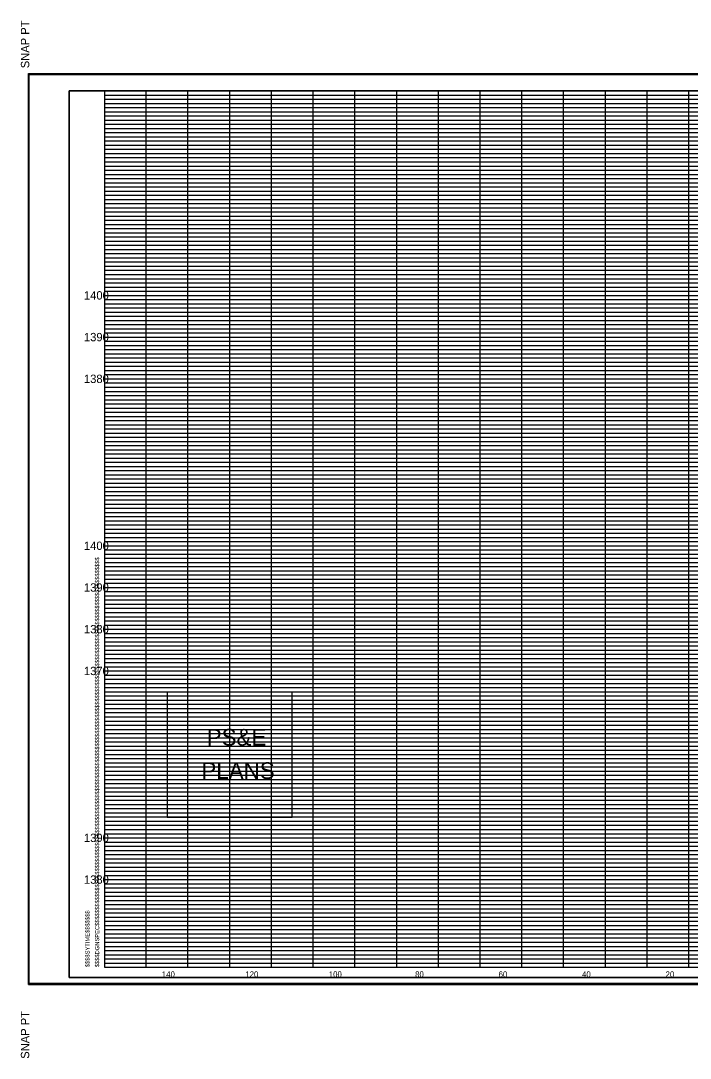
# Model space of a CAD drawing. Extents: x 980 to 1324, y 978 to 1497.
# Drawn here: x 979.9 to 1140.3, y 978.2 to 1226.8 of the extents above; entities that cross this region are included whole.
import ezdxf

# ---------------------------------------------------------------- set-up
doc = ezdxf.new("R2010")
doc.units = 0
for name, color, linetype in [('DESIGN - SHEET - Corner Text', 7, 'Continuous'), ('DESIGN - SHEET - Light Grid', 7, 'Continuous'), ('DESIGN - SHEET - Linework', 7, 'Continuous'), ('DESIGN - SHEET - Plot Shape', 7, 'Continuous'), ('DESIGN - TYPICAL - Text', 7, 'Continuous')]:
    doc.layers.add(name, color=color, linetype=linetype)

# ---------------------------------------------------------------- blocks, each defined once
blk = doc.blocks.new('XSTSHT')
at = {"layer": 'DESIGN - SHEET - Light Grid'}
for p, q in [((0, 20.9), (8, 20.9)), ((8, 20.9), (16, 20.9)), ((0, 20.8), (8, 20.8)), ((0, 20.7), (8, 20.7)), ((8, 20.8), (16, 20.8)), ((8, 20.7), (16, 20.7)), ((0, 20.6), (8, 20.6)), ((0, 20.5), (8, 20.5)), ((0, 20.4), (8, 20.4)), ((8, 20.6), (16, 20.6)), ((8, 20.5), (16, 20.5)), ((8, 20.4), (16, 20.4)), ((0, 20.3), (8, 20.3)), ((0, 20.2), (8, 20.2)), ((8, 20.3), (16, 20.3)), ((8, 20.2), (16, 20.2)), ((0, 20.1), (8, 20.1)), ((0, 19.9), (8, 19.9)), ((8, 20.1), (16, 20.1)), ((8, 19.9), (16, 19.9)), ((0, 19.8), (8, 19.8)), ((0, 19.7), (8, 19.7)), ((8, 19.8), (16, 19.8)), ((8, 19.7), (16, 19.7)), ((0, 19.6), (8, 19.6)), ((0, 19.5), (8, 19.5)), ((0, 19.4), (8, 19.4)), ((8, 19.6), (16, 19.6)), ((8, 19.5), (16, 19.5)), ((8, 19.4), (16, 19.4)), ((0, 19.3), (8, 19.3)), ((0, 19.2), (8, 19.2)), ((8, 19.3), (16, 19.3)), ((8, 19.2), (16, 19.2)), ((0, 19.1), (8, 19.1)), ((0, 18.9), (8, 18.9)), ((8, 19.1), (16, 19.1)), ((8, 18.9), (16, 18.9)), ((0, 18.8), (8, 18.8)), ((0, 18.7), (8, 18.7)), ((8, 18.8), (16, 18.8)), ((8, 18.7), (16, 18.7)), ((0, 18.6), (8, 18.6)), ((0, 18.5), (8, 18.5)), ((0, 18.4), (8, 18.4)), ((8, 18.6), (16, 18.6)), ((8, 18.5), (16, 18.5)), ((8, 18.4), (16, 18.4)), ((0, 18.3), (8, 18.3)), ((0, 18.2), (8, 18.2)), ((8, 18.3), (16, 18.3)), ((8, 18.2), (16, 18.2)), ((0, 18.1), (8, 18.1)), ((8, 18.1), (16, 18.1)), ((0, 17.9), (8, 17.9)), ((0, 17.8), (8, 17.8)), ((0, 17.7), (8, 17.7)), ((8, 17.9), (16, 17.9)), ((8, 17.8), (16, 17.8)), ((8, 17.7), (16, 17.7)), ((0, 17.6), (8, 17.6)), ((0, 17.5), (8, 17.5)), ((8, 17.6), (16, 17.6)), ((8, 17.5), (16, 17.5)), ((0, 17.4), (8, 17.4)), ((0, 17.3), (8, 17.3)), ((0, 17.2), (8, 17.2)), ((8, 17.4), (16, 17.4)), ((8, 17.3), (16, 17.3)), ((8, 17.2), (16, 17.2)), ((0, 17.1), (8, 17.1)), ((8, 17.1), (16, 17.1)), ((0, 16.9), (8, 16.9)), ((0, 16.8), (8, 16.8)), ((0, 16.7), (8, 16.7)), ((8, 16.9), (16, 16.9)), ((8, 16.8), (16, 16.8)), ((8, 16.7), (16, 16.7)), ((0, 16.6), (8, 16.6)), ((0, 16.5), (8, 16.5)), ((8, 16.6), (16, 16.6)), ((8, 16.5), (16, 16.5)), ((0, 16.4), (8, 16.4)), ((0, 16.3), (8, 16.3)), ((0, 16.2), (8, 16.2)), ((8, 16.4), (16, 16.4)), ((8, 16.3), (16, 16.3)), ((8, 16.2), (16, 16.2)), ((0, 16.1), (8, 16.1)), ((8, 16.1), (16, 16.1)), ((0, 15.9), (8, 15.9)), ((0, 15.8), (8, 15.8)), ((0, 15.7), (8, 15.7)), ((8, 15.9), (16, 15.9)), ((8, 15.8), (16, 15.8)), ((8, 15.7), (16, 15.7)), ((0, 15.6), (8, 15.6)), ((0, 15.5), (8, 15.5)), ((8, 15.6), (16, 15.6)), ((8, 15.5), (16, 15.5)), ((0, 15.4), (8, 15.4)), ((0, 15.3), (8, 15.3)), ((0, 15.2), (8, 15.2)), ((8, 15.4), (16, 15.4)), ((8, 15.3), (16, 15.3)), ((8, 15.2), (16, 15.2)), ((0, 15.1), (8, 15.1)), ((8, 15.1), (16, 15.1)), ((0, 14.9), (8, 14.9)), ((0, 14.8), (8, 14.8)), ((0, 14.7), (8, 14.7)), ((8, 14.9), (16, 14.9)), ((8, 14.8), (16, 14.8)), ((8, 14.7), (16, 14.7)), ((0, 14.6), (8, 14.6)), ((0, 14.5), (8, 14.5)), ((8, 14.6), (16, 14.6)), ((8, 14.5), (16, 14.5)), ((0, 14.4), (8, 14.4)), ((0, 14.3), (8, 14.3)), ((0, 14.2), (8, 14.2)), ((8, 14.4), (16, 14.4)), ((8, 14.3), (16, 14.3)), ((8, 14.2), (16, 14.2)), ((0, 14.1), (8, 14.1)), ((8, 14.1), (16, 14.1)), ((0, 13.9), (8, 13.9)), ((0, 13.8), (8, 13.8)), ((0, 13.7), (8, 13.7)), ((8, 13.9), (16, 13.9)), ((8, 13.8), (16, 13.8)), ((8, 13.7), (16, 13.7)), ((0, 13.6), (8, 13.6)), ((0, 13.5), (8, 13.5)), ((8, 13.6), (16, 13.6)), ((8, 13.5), (16, 13.5)), ((0, 13.4), (8, 13.4)), ((0, 13.3), (8, 13.3)), ((0, 13.2), (8, 13.2)), ((8, 13.4), (16, 13.4)), ((8, 13.3), (16, 13.3)), ((8, 13.2), (16, 13.2)), ((0, 13.1), (8, 13.1)), ((8, 13.1), (16, 13.1)), ((0, 12.9), (8, 12.9)), ((0, 12.8), (8, 12.8)), ((0, 12.7), (8, 12.7)), ((8, 12.9), (16, 12.9)), ((8, 12.8), (16, 12.8)), ((8, 12.7), (16, 12.7)), ((0, 12.6), (8, 12.6)), ((0, 12.5), (8, 12.5)), ((8, 12.6), (16, 12.6)), ((8, 12.5), (16, 12.5)), ((0, 12.4), (8, 12.4)), ((0, 12.3), (8, 12.3)), ((0, 12.2), (8, 12.2)), ((8, 12.4), (16, 12.4)), ((8, 12.3), (16, 12.3)), ((8, 12.2), (16, 12.2)), ((0, 12.1), (8, 12.1)), ((8, 12.1), (16, 12.1)), ((0, 11.9), (8, 11.9)), ((0, 11.8), (8, 11.8)), ((0, 11.7), (8, 11.7)), ((8, 11.9), (16, 11.9)), ((8, 11.8), (16, 11.8)), ((8, 11.7), (16, 11.7)), ((0, 11.6), (8, 11.6)), ((0, 11.5), (8, 11.5)), ((8, 11.6), (16, 11.6)), ((8, 11.5), (16, 11.5)), ((0, 11.4), (8, 11.4)), ((0, 11.3), (8, 11.3)), ((0, 11.2), (8, 11.2)), ((8, 11.4), (16, 11.4)), ((8, 11.3), (16, 11.3)), ((8, 11.2), (16, 11.2)), ((0, 11.1), (8, 11.1)), ((8, 11.1), (16, 11.1)), ((0, 10.9), (8, 10.9)), ((0, 10.8), (8, 10.8)), ((0, 10.7), (8, 10.7)), ((8, 10.9), (16, 10.9)), ((8, 10.8), (16, 10.8)), ((8, 10.7), (16, 10.7)), ((0, 10.6), (8, 10.6)), ((0, 10.5), (8, 10.5)), ((8, 10.6), (16, 10.6)), ((8, 10.5), (16, 10.5)), ((0, 10.4), (8, 10.4)), ((0, 10.3), (8, 10.3)), ((0, 10.2), (8, 10.2)), ((8, 10.4), (16, 10.4)), ((8, 10.3), (16, 10.3)), ((8, 10.2), (16, 10.2)), ((0, 10.1), (8, 10.1)), ((8, 10.1), (16, 10.1)), ((0, 9.9), (8, 9.9)), ((0, 9.8), (8, 9.8)), ((0, 9.7), (8, 9.7)), ((8, 9.9), (16, 9.9)), ((8, 9.8), (16, 9.8)), ((8, 9.7), (16, 9.7)), ((0, 9.6), (8, 9.6)), ((0, 9.5), (8, 9.5)), ((8, 9.6), (16, 9.6)), ((8, 9.5), (16, 9.5)), ((0, 9.4), (8, 9.4)), ((0, 9.3), (8, 9.3)), ((0, 9.2), (8, 9.2)), ((8, 9.4), (16, 9.4)), ((8, 9.3), (16, 9.3)), ((8, 9.2), (16, 9.2)), ((0, 9.1), (8, 9.1)), ((8, 9.1), (16, 9.1)), ((0, 8.9), (8, 8.9)), ((0, 8.8), (8, 8.8)), ((8, 8.9), (16, 8.9)), ((8, 8.8), (16, 8.8)), ((0, 8.7), (8, 8.7)), ((0, 8.6), (8, 8.6)), ((0, 8.5), (8, 8.5)), ((8, 8.7), (16, 8.7)), ((8, 8.6), (16, 8.6)), ((8, 8.5), (16, 8.5)), ((0, 8.4), (8, 8.4)), ((0, 8.3), (8, 8.3)), ((8, 8.4), (16, 8.4)), ((8, 8.3), (16, 8.3)), ((0, 8.2), (8, 8.2)), ((0, 8.1), (8, 8.1)), ((8, 8.2), (16, 8.2)), ((8, 8.1), (16, 8.1)), ((0, 7.9), (8, 7.9)), ((0, 7.8), (8, 7.8)), ((8, 7.9), (16, 7.9)), ((8, 7.8), (16, 7.8)), ((0, 7.7), (8, 7.7)), ((0, 7.6), (8, 7.6)), ((0, 7.5), (8, 7.5)), ((8, 7.7), (16, 7.7)), ((8, 7.6), (16, 7.6)), ((8, 7.5), (16, 7.5)), ((0, 7.4), (8, 7.4)), ((0, 7.3), (8, 7.3)), ((8, 7.4), (16, 7.4)), ((8, 7.3), (16, 7.3)), ((0, 7.2), (8, 7.2)), ((0, 7.1), (8, 7.1)), ((8, 7.2), (16, 7.2)), ((8, 7.1), (16, 7.1)), ((0, 6.9), (8, 6.9)), ((0, 6.8), (8, 6.8)), ((8, 6.9), (16, 6.9)), ((8, 6.8), (16, 6.8)), ((0, 6.7), (8, 6.7)), ((0, 6.6), (8, 6.6)), ((0, 6.5), (8, 6.5)), ((8, 6.7), (16, 6.7)), ((8, 6.6), (16, 6.6)), ((8, 6.5), (16, 6.5)), ((0, 6.4), (8, 6.4)), ((0, 6.3), (8, 6.3)), ((8, 6.4), (16, 6.4)), ((8, 6.3), (16, 6.3)), ((0, 6.2), (8, 6.2)), ((0, 6.1), (8, 6.1)), ((8, 6.2), (16, 6.2)), ((8, 6.1), (16, 6.1)), ((0, 5.9), (8, 5.9)), ((0, 5.8), (8, 5.8)), ((8, 5.9), (16, 5.9)), ((8, 5.8), (16, 5.8)), ((0, 5.7), (8, 5.7)), ((0, 5.6), (8, 5.6)), ((0, 5.5), (8, 5.5)), ((8, 5.7), (16, 5.7)), ((8, 5.6), (16, 5.6)), ((8, 5.5), (16, 5.5)), ((0, 5.4), (8, 5.4)), ((0, 5.3), (8, 5.3)), ((8, 5.4), (16, 5.4)), ((8, 5.3), (16, 5.3)), ((0, 5.2), (8, 5.2)), ((0, 5.1), (8, 5.1)), ((8, 5.2), (16, 5.2)), ((8, 5.1), (16, 5.1)), ((0, 4.9), (8, 4.9)), ((0, 4.8), (8, 4.8)), ((8, 4.9), (16, 4.9)), ((8, 4.8), (16, 4.8)), ((0, 4.7), (8, 4.7)), ((0, 4.6), (8, 4.6)), ((0, 4.5), (8, 4.5)), ((8, 4.7), (16, 4.7)), ((8, 4.6), (16, 4.6)), ((8, 4.5), (16, 4.5)), ((0, 4.4), (8, 4.4)), ((0, 4.3), (8, 4.3)), ((8, 4.4), (16, 4.4)), ((8, 4.3), (16, 4.3)), ((0, 4.2), (8, 4.2)), ((0, 4.1), (8, 4.1)), ((8, 4.2), (16, 4.2)), ((8, 4.1), (16, 4.1)), ((0, 3.9), (8, 3.9)), ((0, 3.8), (8, 3.8)), ((8, 3.9), (16, 3.9)), ((8, 3.8), (16, 3.8)), ((0, 3.7), (8, 3.7)), ((0, 3.6), (8, 3.6)), ((0, 3.5), (8, 3.5)), ((8, 3.7), (16, 3.7)), ((8, 3.6), (16, 3.6)), ((8, 3.5), (16, 3.5)), ((0, 3.4), (8, 3.4)), ((0, 3.3), (8, 3.3)), ((8, 3.4), (16, 3.4)), ((8, 3.3), (16, 3.3)), ((0, 3.2), (8, 3.2)), ((0, 3.1), (8, 3.1)), ((8, 3.2), (16, 3.2)), ((8, 3.1), (16, 3.1)), ((0, 2.9), (8, 2.9)), ((0, 2.8), (8, 2.8)), ((8, 2.9), (16, 2.9)), ((8, 2.8), (16, 2.8)), ((0, 2.7), (8, 2.7)), ((0, 2.6), (8, 2.6)), ((0, 2.5), (8, 2.5)), ((8, 2.7), (16, 2.7)), ((8, 2.6), (16, 2.6)), ((8, 2.5), (16, 2.5)), ((0, 2.4), (8, 2.4)), ((0, 2.3), (8, 2.3)), ((8, 2.4), (16, 2.4)), ((8, 2.3), (16, 2.3)), ((0, 2.2), (8, 2.2)), ((0, 2.1), (8, 2.1)), ((8, 2.2), (16, 2.2)), ((8, 2.1), (16, 2.1)), ((0, 1.9), (8, 1.9)), ((0, 1.8), (8, 1.8)), ((8, 1.9), (16, 1.9)), ((8, 1.8), (16, 1.8)), ((0, 1.7), (8, 1.7)), ((0, 1.6), (8, 1.6)), ((0, 1.5), (8, 1.5)), ((8, 1.7), (16, 1.7)), ((8, 1.6), (16, 1.6)), ((8, 1.5), (16, 1.5)), ((0, 1.4), (8, 1.4)), ((0, 1.3), (8, 1.3)), ((8, 1.4), (16, 1.4)), ((8, 1.3), (16, 1.3)), ((0, 1.2), (8, 1.2)), ((0, 1.1), (8, 1.1)), ((8, 1.2), (16, 1.2)), ((8, 1.1), (16, 1.1)), ((0, 0.9), (8, 0.9)), ((0, 0.8), (8, 0.8)), ((8, 0.9), (16, 0.9)), ((8, 0.8), (16, 0.8)), ((0, 0.7), (8, 0.7)), ((0, 0.6), (8, 0.6)), ((0, 0.5), (8, 0.5)), ((8, 0.7), (16, 0.7)), ((8, 0.6), (16, 0.6)), ((8, 0.5), (16, 0.5)), ((0, 0.4), (8, 0.4)), ((0, 0.3), (8, 0.3)), ((8, 0.4), (16, 0.4)), ((8, 0.3), (16, 0.3)), ((0, 0.2), (8, 0.2)), ((0, 0.1), (8, 0.1)), ((8, 0.2), (16, 0.2)), ((8, 0.1), (16, 0.1))]:
    blk.add_line(p, q, dxfattribs=at)
at = {"layer": 'DESIGN - SHEET - Linework'}
for p, q in [((-1.823, -0.414), (-1.823, 21.414)), ((-1.823, 21.414), (32.217, 21.414)), ((1, 0), (1, 21)), ((2, 0), (2, 21)), ((3, 0), (3, 21)), ((4, 0), (4, 21)), ((5, 0), (5, 21)), ((6, 0), (6, 21)), ((7, 0), (7, 21)), ((8, 0), (8, 21)), ((9, 0), (9, 21)), ((10, 0), (10, 21)), ((11, 0), (11, 21)), ((12, 0), (12, 21)), ((13, 0), (13, 21)), ((14, 0), (14, 21)), ((0, 20), (28, 20)), ((0, 19), (32, 19)), ((0, 18), (32, 18)), ((0, 17), (32, 17)), ((0, 16), (32, 16)), ((0, 15), (32, 15)), ((0, 14), (32, 14)), ((0, 13), (32, 13)), ((0, 12), (32, 12)), ((0, 11), (32, 11)), ((0, 10), (32, 10)), ((0, 9), (32, 9)), ((0, 8), (32, 8)), ((0, 7), (32, 7)), ((0, 6), (32, 6)), ((0, 5), (32, 5)), ((0, 4), (32, 4)), ((0, 3), (32, 3)), ((0, 2), (32, 2)), ((0, 1), (32, 1)), ((-1.823, -0.414), (32.217, -0.414))]:
    blk.add_line(p, q, dxfattribs=at)
blk.add_lwpolyline([(0, 21), (0, 0), (32, 0), (32, 21), (0, 21)], dxfattribs=at)
at = {"layer": 'DESIGN - SHEET - Plot Shape'}
for points in [[(-1.803, 21.394), (32.197, 21.394), (32.197, -0.394), (-1.803, -0.394)], [(-0.85, 21), (32, 21), (32, -0.25), (-0.85, -0.25)]]:
    blk.add_lwpolyline(points, close=True, dxfattribs=at)
at = {"layer": 'DESIGN - SHEET - Corner Text'}
for s, height, p in [('  SNAP PT', 0.2, (-1.803, 21.394)), ('$$$$DGNSPEC$$$$$$$$$$$$$$$$$$$$$$$$$$$$$$$$$$$$$$$$$$$$$$$$$$$$$$$$$$$$$$$$$$$$$$$$$$$$$$$$$$$$$$$$$$$$$$$$$$$$$$$$$$$$$$$$$$$', 0.100002, (-0.126, 0)), ('$$$$SYTIME$$$$$$$', 0.1, (-0.358, 0)), ('SNAP PT  ', 0.2, (-1.803, -2.194))]:
    blk.add_text(s, height=height, rotation=90, dxfattribs=at).set_placement(p)

msp = doc.modelspace()

# ---------------------------------------------------------------- linework, layer by layer
at = {"layer": 'DESIGN - SHEET - Corner Text'}
msp.add_lwpolyline([(1014.98, 1065.93), (1014.98, 1035.93), (1044.98, 1035.93), (1044.98, 1065.93)], close=True, dxfattribs=at)
at = {"layer": 'DESIGN - SHEET - Plot Shape'}
msp.add_lwpolyline([(991.5, 997.5), (1320, 997.5), (1320, 1210), (991.5, 1210)], close=True, dxfattribs=at)

# ---------------------------------------------------------------- block references
at = {"layer": 'DESIGN - TYPICAL - Text', "xscale": 10, "yscale": 10}
msp.add_blockref('XSTSHT', (1000, 1000), dxfattribs=at)

# ---------------------------------------------------------------- texts
at = {"layer": 'DESIGN - SHEET - Corner Text'}
for s, p in [('PS&E', (1024.5, 1053.11)), ('PLANS', (1023.22, 1045.11))]:
    msp.add_text(s, height=4, dxfattribs=at).set_placement(p)
at = {"layer": 'DESIGN - TYPICAL - Text'}
for s, height, p in [('     1400     ', 2, (991.37, 1160)), ('     1390     ', 2, (991.37, 1150)), ('     1380     ', 2, (991.37, 1140)), ('     1400     ', 2, (991.37, 1100)), ('     1390     ', 2, (991.37, 1090)), ('     1380     ', 2, (991.37, 1080)), ('     1370     ', 2, (991.37, 1070)), ('     1390     ', 2, (991.37, 1030)), ('     1380     ', 2, (991.37, 1020)), ('     140     ', 1.4, (1011.14, 997.6)), ('     120     ', 1.4, (1031.14, 997.6)), ('     100     ', 1.4, (1051.14, 997.6)), ('     80     ', 1.4, (1071.82, 997.6)), ('     60     ', 1.4, (1091.82, 997.6)), ('     40     ', 1.4, (1111.82, 997.6)), ('     20     ', 1.4, (1131.82, 997.6))]:
    msp.add_text(s, height=height, dxfattribs=at).set_placement(p)

doc.saveas('drawing.dxf')
